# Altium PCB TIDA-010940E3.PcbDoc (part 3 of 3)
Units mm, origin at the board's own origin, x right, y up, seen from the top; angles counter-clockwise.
Board outline 71.12 x 63.5 mm, 2 copper layers (Top Layer, Bottom Layer), stack 1.382 mm thick; 136 components, 118 nets, 421 pads, 150 vias.
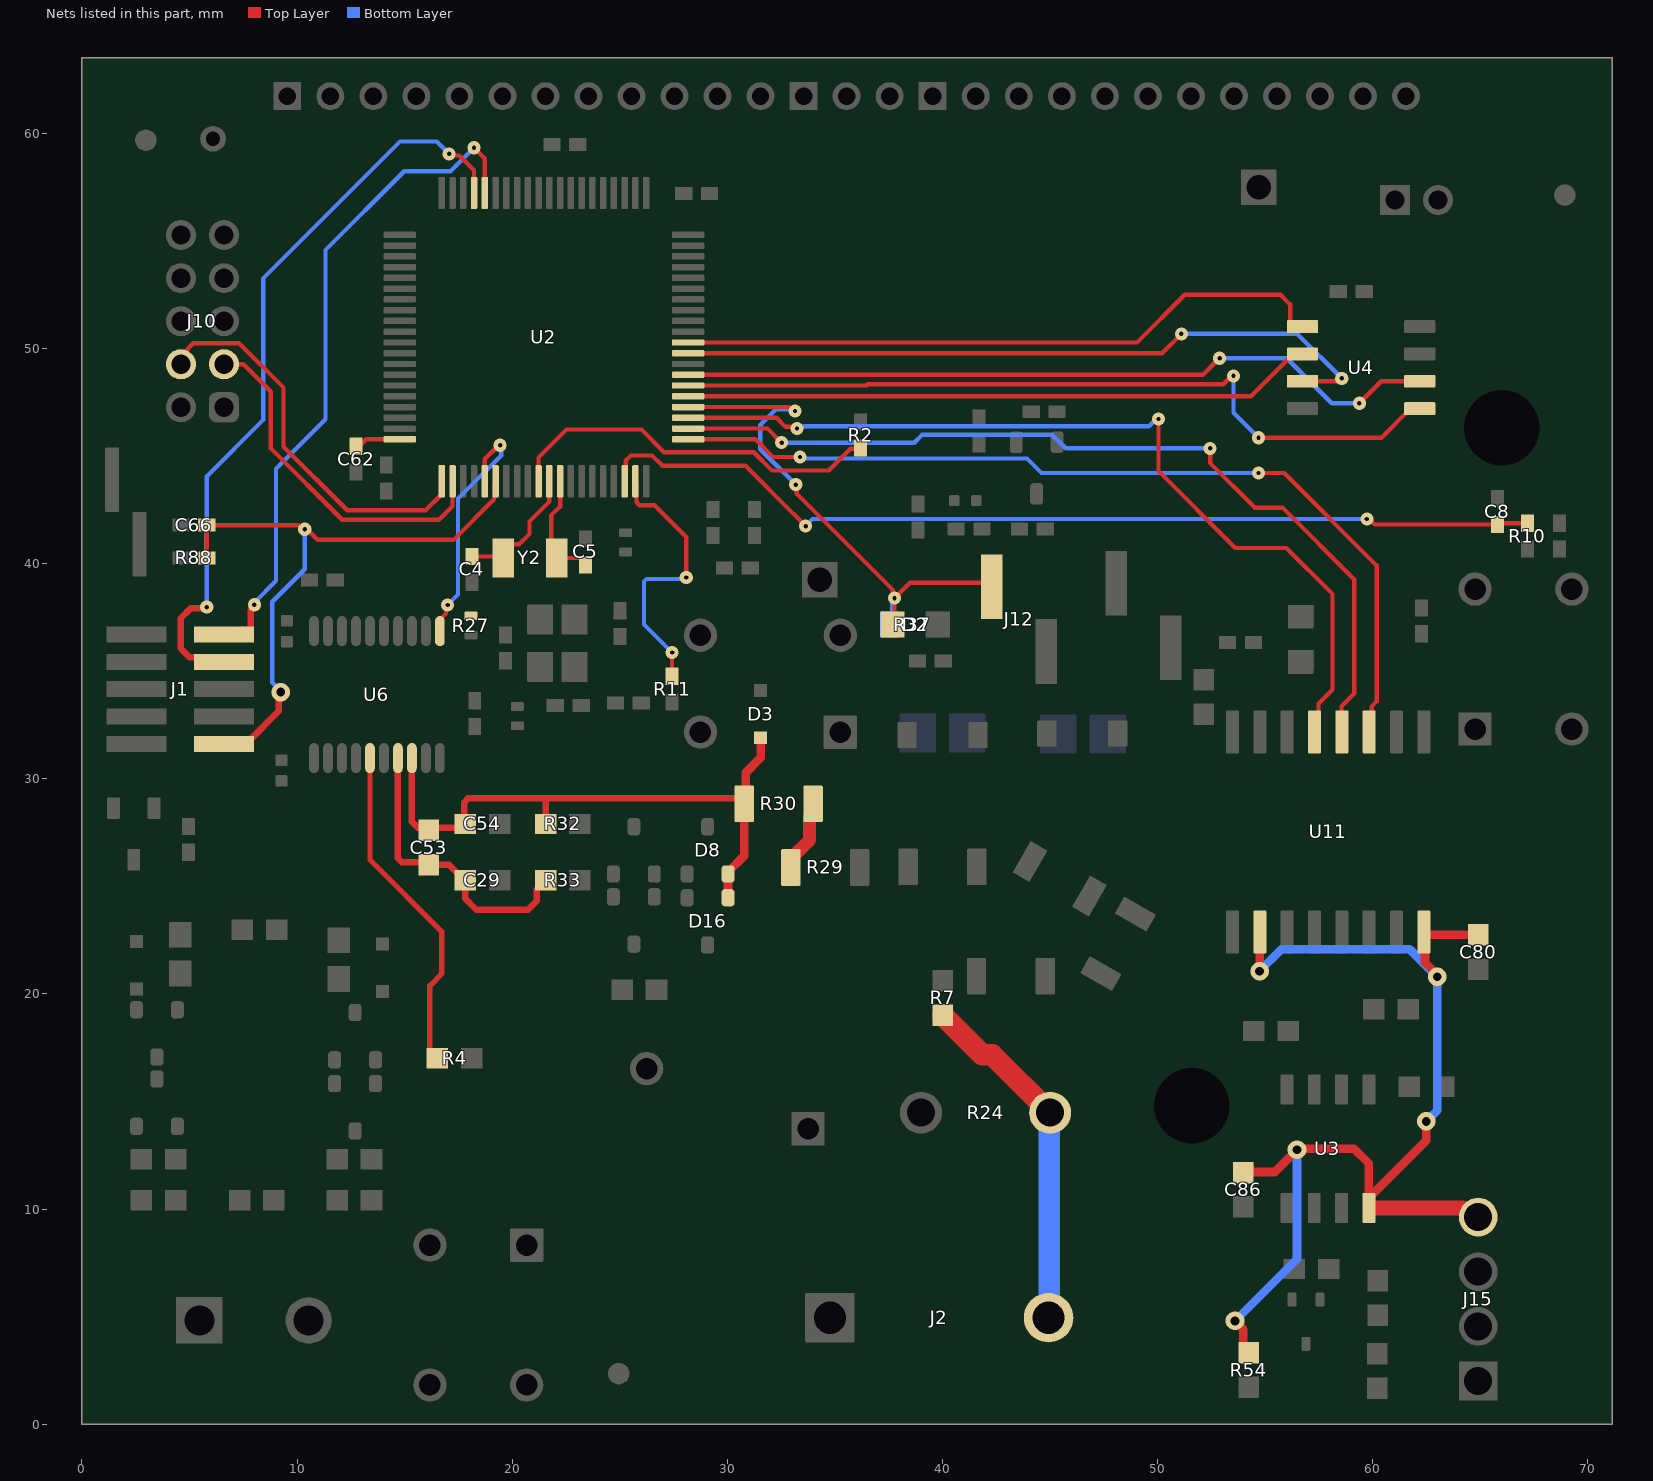
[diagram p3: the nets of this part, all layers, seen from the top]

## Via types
v1: diameter 0.61, hole 0.203, Top Layer to Bottom Layer, tented both sides, 113 vias
v2: diameter 0.61, hole 0.203, Top Layer to Bottom Layer, 22 vias
v3: diameter 0.864, hole 0.406, Top Layer to Bottom Layer, 8 vias
v4: diameter 0.864, hole 0.3, Top Layer to Bottom Layer, tented both sides, 4 vias
v5: diameter 0.864, hole 0.406, Top Layer to Bottom Layer, tented both sides, 3 vias

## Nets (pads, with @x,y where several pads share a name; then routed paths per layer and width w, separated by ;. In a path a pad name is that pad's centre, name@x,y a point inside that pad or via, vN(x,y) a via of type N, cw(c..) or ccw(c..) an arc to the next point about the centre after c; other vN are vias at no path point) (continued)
NetR29_1: R29.1 R30.1 | length 3.4
  Top Layer w0.6: R29.1@32.95,25.875 32.95,26.275 33.825,27.15 33.825,28.269 33.985,28.429 R30.1@33.985,28.829
nRST: C66.1 J1.10 R88.1 U2.6 | length 29.3
  Top Layer w0.2: R88.1@5.807,40.259 C66.1@5.807,41.775 ; C66.1@5.807,41.783 C66.1@5.807,41.775 ; U2.6@19.228,43.824 19.178,43.774 19.178,43.077 19.158,43.057 19.158,42.987 17.271,41.1 10.963,41.1 10.47,41.592 10.249,41.592 10.066,41.775 C66.1@5.807,41.775
  Top Layer w0.3: J1.10@6.607,31.623 6.786,31.802 7.811,31.802 9.152,33.143 9.152,33.927 v5(9.25,34.025)
  Bottom Layer w0.2: v5(9.25,34.025) 9.25,34.074 8.85,34.474 8.85,38.225 10.36,39.735 v1(10.36,41.592)
PA0: J10.4 U2.1 | length 18.5
  Top Layer w0.2: J10.4@4.604,49.262 4.604,49.587 4.91,49.893 4.91,49.971 5.182,50.242 7.308,50.242 9.375,48.175 9.375,45.431 12.331,42.475 15.979,42.475 16.728,43.224 U2.1@16.728,43.824
PA1: J10.3 U2.2 | length 16.6
  Top Layer w0.2: J10.3@6.604,49.262 7.509,49.262 8.786,47.985 8.786,45.351 12.102,42.036 16.598,42.036 17.228,42.665 U2.2@17.228,43.824
PA2_ROSC: R2.2 U2.10 | length 17.8
  Top Layer w0.2: U2.10@21.228,43.824 21.228,44.924 22.531,46.227 26.01,46.227 27.062,45.175 31.23,45.175 32.082,44.323 34.713,44.323 34.83,44.44 34.83,44.446 35.712,45.329 36.15,45.329 R2.2@36.195,45.374
PA3_LFXIN: C4.2 U2.11 Y2.2 | length 6.1
  Top Layer w0.2: C4.2@18.125,40.325 19.512,40.325 Y2.2@19.578,40.259 19.578,40.503 19.978,40.903 20.332,40.903 20.802,41.373 20.802,41.952 21.728,42.878 U2.11@21.728,43.824
PA4_LFXOUT: C5.2 U2.12 Y2.1 | length 5.2
  Top Layer w0.2: U2.12@22.228,43.824 22.228,42.646 21.811,42.229 21.811,40.526 Y2.1@22.078,40.259 23.168,40.259 23.368,40.059 C5.2@23.368,40.04
REACT: D2.1 J12.1 R37.1 U2.24 | length 24.8
  Top Layer w0.203: U2.24@28.178,47.274 32.849,47.274 33.032,47.091 v2(33.142,47.091) ; v2(33.179,43.668) 33.218,43.629 33.218,43.252 37.696,38.773 37.696,38.465 v1(37.77,38.391) ; D2.1@37.695,37.166 37.77,37.241 v1(37.77,38.391) ; J12.1@42.291,38.913 42.093,39.111 38.49,39.111 38.407,39.029 v1(37.77,38.391)
  Bottom Layer w0.203: v2(33.142,47.091) 33.065,47.168 32.262,47.168 31.535,46.442 31.535,45.312 v2(33.179,43.668) ; R37.1@37.666,37.291 v1@37.666,38.366
S\Y\N\C\/R\E\S\E\T\: U2.5 U6.11 | length 11.8
  Top Layer w0.2: U6.11@16.641,36.859 16.641,37.402 16.922,37.682 16.922,37.997 v1(17,38.075) ; U2.5@18.728,43.824 18.728,44.853 19.375,45.5 v1(19.439,45.5)
  Bottom Layer w0.2: v1(17,38.075) 17.484,38.559 17.484,43.02 19.489,45.024 19.489,45.45 v1(19.439,45.5)
Serial_RE_DE: U2.21 U11.3 | length 42.3
  Top Layer w0.2: U2.21@28.178,45.774 31.303,45.774 32.127,44.95 v1(33.375,44.95) ; v2(54.684,44.211) 55.883,44.211 60.178,39.916 60.178,33.591 59.943,33.356 59.943,32.288 U11.3@59.83,32.175
  Bottom Layer w0.2: v1(33.375,44.95) 33.442,44.883 43.929,44.883 44.601,44.211 v2(54.684,44.211)
Serial_RX: U2.23 U11.5 | length 41.9
  Top Layer w0.2: U2.23@28.178,46.774 32.288,46.774 32.71,46.353 33.161,46.353 v1(33.24,46.274) ; v2(50.038,46.72) 50.038,44.296 53.609,40.725 55.978,40.725 58.125,38.578 58.125,34.136 57.473,33.484 57.473,32.38 U11.5@57.277,32.184
  Bottom Layer w0.2: v1(33.24,46.274) 33.318,46.353 33.539,46.353 33.562,46.375 49.582,46.375 49.927,46.72 v2(50.038,46.72)
Serial_TX: U2.22 U11.4 | length 41.9
  Top Layer w0.2: U2.22@28.178,46.274 31.867,46.274 v1(32.523,45.618) ; v2(52.438,45.355) 52.438,44.674 54.512,42.6 55.8,42.6 59.134,39.266 59.134,33.957 58.547,33.37 U11.4@58.547,32.184
  Bottom Layer w0.2: v1(32.523,45.618) 38.687,45.618 39.048,45.979 45.1,45.979 45.725,45.355 v2(52.438,45.355)
SPI1_CS0: U2.30 U4.1 | length 30.6
  Top Layer w0.2: U2.30@28.178,50.274 49.041,50.274 51.262,52.495 55.706,52.495 56.157,52.044 56.157,51.212 56.357,51.012 U4.1@56.731,51.012
SPI1_PICO: U2.26 U4.5 | length 37
  Top Layer w0.203: U2.26@28.178,48.274 36.466,48.274 36.528,48.336 53.052,48.336 53.441,48.725 v1(53.525,48.725) v1@53.506,48.706 ; v1(54.684,45.845) 60.399,45.845 61.756,47.202 U4.5@62.181,47.202
  Bottom Layer w0.203: v1(53.525,48.725) 53.525,47.004 v1(54.684,45.845)
SPI1_POCI: U2.25 U4.2 | length 29.4
  Top Layer w0.2: U2.25@28.178,47.774 54.338,47.774 56.306,49.742 U4.2@56.731,49.742
SPI1_SCLK: U2.27 U4.6 | length 36.2
  Top Layer w0.2: U2.27@28.178,48.774 52.111,48.774 v1(52.881,49.544) ; v1(59.373,47.451) 60.394,48.472 U4.6@62.181,48.472
  Top Layer w0.203: 52.438,49.124 52.858,49.544 v1(52.881,49.544)
  Bottom Layer w0.2: v1(52.881,49.544) 55.999,49.544 58.092,47.451 v1(59.373,47.451)
SWCLK: J1.4 U2.57 | length 35.5
  Top Layer w0.2: v1(17.072,59.04) 17.151,58.961 17.544,58.961 18.228,58.278 U2.57@18.228,57.224
  Top Layer w0.3: v1(5.807,37.973) 5.749,37.915 5.052,37.915 4.591,37.454 4.591,36.054 5.009,35.636 6.404,35.636 J1.4@6.607,35.433
  Bottom Layer w0.2: v1(5.807,37.973) 5.807,44.051 8.425,46.669 8.425,53.25 14.792,59.617 16.494,59.617 v1(17.072,59.04)
SWDIO: J1.2 U2.56 | length 31.7
  Top Layer w0.2: v1@18.291,59.325 v1(18.225,59.325) 18.728,58.822 U2.56@18.728,57.224
  Top Layer w0.3: J1.2@6.607,36.703 7.155,36.703 7.375,36.923 7.852,36.923 7.852,37.832 8.02,38 v1(8.02,38.084)
  Bottom Layer w0.2: v1(8.02,38.084) 8.02,38.195 9.025,39.2 9.025,44.404 11.325,46.704 11.325,54.57 14.987,58.232 17.132,58.232 v1(18.225,59.325)
TAMPER_1: C8.1 R10.2 U2.18 | length 44.6
  Top Layer w0.2: U2.18@25.228,43.824 25.278,43.874 25.278,44.784 25.519,45.024 26.501,45.024 26.975,44.55 30.836,44.55 33.058,42.327 ; v2(59.722,42.072) 59.833,42.072 60.087,41.818 C8.1@65.786,41.818 65.843,41.875 R10.2@67.183,41.875
  Top Layer w0.203: 33.058,42.327 33.641,41.745 v1(33.641,41.742)
  Bottom Layer w0.2: v1(33.641,41.742) 33.641,41.75 33.962,42.072 v2(59.722,42.072)
TAMPER_2: R11.2 U2.19 | length 12.8
  Top Layer w0.2: U2.19@25.728,43.824 25.778,43.774 25.778,42.852 25.919,42.711 26.609,42.711 28.091,41.229 v1(28.091,39.35) ; R11.2@27.432,34.763 v1(27.432,35.865)
  Bottom Layer w0.2: v1(27.432,35.865) 26.129,37.167 26.129,39.162 26.246,39.279 28.02,39.279 v1(28.091,39.35)
V_PHASE_A: J2.2 R7.1 R24.1 | length 16.4
  Top Layer w1: R7.1@40.005,19.012 41.842,17.175 42.303,17.175 R24.1@45,14.478
  Bottom Layer w1: J2.2@44.93,4.95 44.965,4.985 44.965,14.443 R24.1@45,14.478
VCC_ISO_RS: C80.1 C86.1 J15.4 R54.2 U3.8 U11.10 U11.16 | length 52.5
  Top Layer w0.4: v3(53.594,4.801) 53.98,4.415 53.98,3.564 R54.2@54.229,3.315 ; C86.1@53.975,11.697 C86.1@53.975,11.722 ; C86.1@54.275,11.997 54.25,11.997 C86.1@53.975,11.722 ; v3(54.737,21.057) U11.10@54.737,22.708 ; v3(56.476,12.752) 55.446,11.722 C86.1@53.975,11.722 ; v3@56.476,12.802 59.13,12.802 59.817,12.115 U3.8@59.817,10.052 ; U3.8@59.917,10.152 59.917,10.616 62.484,13.183 v3(62.484,14.07) ; v3(62.996,20.792) 62.996,20.881 62.423,21.455 62.423,22.642 62.357,22.708 62.395,22.746 C80.1@64.897,22.746
  Top Layer w0.7: U3.8@60.066,10.052 64.174,10.052 64.599,9.627 J15.4@64.897,9.627
  Bottom Layer w0.4: v3(53.594,4.801) 56.476,7.683 v3(56.476,12.752) ; v3(54.737,21.057) 55.753,22.073 61.715,22.073 v3(62.996,20.792) 62.996,14.583 v3(62.484,14.07)
VCORE: C62.2 U2.80 | length 2
  Top Layer w0.2: C62.2@12.95,45.402 12.95,45.502 13.222,45.774 U2.80@14.778,45.774
VN: C29.2 C53.2 R33.2 U6.7 | length 13.8
  Top Layer w0.3: U6.7@14.691,30.959 14.691,26.3 14.867,26.124 C53.2@16.129,26.124 ; C53.2@16.129,25.997 17.068,25.997 17.792,25.273 C29.2@17.817,25.273 17.817,24.433 18.336,23.914 20.739,23.914 21.146,24.321 21.146,24.871 21.2,24.925 21.2,24.95 21.525,25.275 R33.2@21.55,25.275
VN_TMP63: R4.2 U6.5 | length 15.7
  Top Layer w0.25: U6.5@13.391,30.959 13.391,26.234 16.725,22.9 16.725,20.925 16.175,20.375 16.175,17.35 R4.2@16.525,17
VP: C53.1 C54.1 D3.2 D8.2 D16.1 R30.2 R32.2 U6.8 | length 29
  Top Layer w0.3: U6.8@15.341,30.959 15.341,28.004 15.621,27.724 16.129,27.724 17.704,27.724 17.742,27.686 17.767,27.686 17.767,28.907 17.943,29.083 21.552,29.083 21.667,29.083 ; R32.2@21.552,27.686 21.552,28.968 21.667,29.083 ; R30.2@30.451,29.083 21.667,29.083
  Top Layer w0.4: D16.1@30.033,24.468 D8.2@30.033,25.57 30.033,25.67 30.785,26.422 R30.2@30.785,28.829 30.854,28.898 30.854,30.279 31.547,30.972 D3.2@31.547,31.902
WP_FLASH: U2.29 U4.3 | length 33.5
  Top Layer w0.203: U2.29@28.178,49.774 50.205,49.774 v1(51.104,50.673) ; U4.3@56.731,48.472 58.421,48.472 v1(58.556,48.607)
  Bottom Layer w0.203: v1(51.104,50.673) 56.49,50.673 v1(58.556,48.607)
XO_HFX: R27.1 | length 0.1
  Top Layer w0.2: R27.1@18.082,37.569 R27.1@18.182,37.569
pads on no net: D6.1 D7.3 D8.3 D10.2 D12.3 D14.3 D15.3 D16.3 FID1.1 FID2.1 FID3.1 H1. H2. J1.6 J1.7 J1.8 LBL1.0 U2.20 U6.9 U6.10 U11.6 U11.11 Y1.2

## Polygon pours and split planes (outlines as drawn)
DGND on Top Layer "TOP_LAYER_DGND_P005" (solid, remove dead copper, pour order 5): 0.889,62.57 0.889,39.751 0.889,31.369 36.755,31.369 70.485,31.369 70.485,62.57
GND_ISO_RS on Top Layer "TOP_LAYER_GND_ISO_RS_P000" (solid, remove dead copper, pour order 0): 52.916,23.724 52.916,0.356 70.231,0.356 70.231,23.724
GND_ISO_RS on Bottom Layer "BOTTOM_LAYER_GND_ISO_RS_P003" (solid, remove dead copper, pour order 3): 53.284,23.597 67.818,23.597 70.231,23.597 70.231,0.483 53.284,0.483
DGND on Bottom Layer "BOTTOM_LAYER_DGND_P004" (solid, remove dead copper, pour order 4): 1.305,62.323 1.305,39.504 1.305,31.122 37.171,31.122 70.901,31.122 70.901,62.323

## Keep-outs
Keep-Out Layer:
  lines w0.254: 0,63.5 0,0 71.12,0
  text ".Layer_Name" at 11.481,-29.045 h1.52

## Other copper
Top Layer:
  text ".Layer_Name" at 11.481,-29.045 h1.52
Bottom Layer:
  text ".Layer_Name" at 11.481,-29.045 h1.52

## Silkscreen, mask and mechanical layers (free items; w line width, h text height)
Top Overlay:
  circle w0.2: c43.942,49.389 r10.2
  text "1-phase SHUNT E-meter" at 23.775,65.776 h2
  text "2mm, 27 pins row" at 54.857,59.588 h0.76
  text "GND" at 65.423,55.827 h0.76 r90
  text "'.PRJ_Number'.PCB_Rev" at 38.188,55.08 h1.91
  text "3V3" at 59.727,54.702 h0.76
  text "BAT-" at 56.809,53.355 h0.76 r90
  text "2mm 5x2" at 9.323,49.277 h0.76 r90
  text "GND" at 1.392,46.095 h0.76 r90
  text "VBAT +" at 32.837,40.573 h0.76 r90
  text "3V3" at 2.635,38.252 h0.76
  text "MENU SW" at 32.627,34.252 h0.76
  text "GND_ISO" at 63.148,19.083 h0.76
  text "DGND" at 8.776,13.106 h0.76 r90
  text "ISO_V" at 64.552,11.854 h0.76
  text "ISO_G" at 67.721,5.902 h0.76 r90
  text "B" at 67.618,3.929 h0.76 r90
  text "CURRENT" at 1.575,1.925 h1 r90
  text "A" at 67.618,1.389 h0.76 r90
  text "DGND" at 31.423,1.277 h0.76 r90
  text "VOLTAGE" at 50.3,0.847 h1.3 r90
  text ".Layer_Name" at 11.481,-29.045 h1.52
Bottom Overlay:
  text ".Layer_Name" at 11.481,-29.045 h1.52
Top Paste:
  text ".Layer_Name" at 11.481,-29.045 h1.52
Bottom Paste:
  text ".Layer_Name" at 11.481,-29.045 h1.52
Top Solder:
  text ".Layer_Name" at 11.481,-29.045 h1.52
  text ".Layer_Name" at 11.481,-29.045 h1.52
Bottom Solder:
  text ".Layer_Name" at 11.481,-29.045 h1.52
Drill Guide:
  text ".Layer_Name" at 11.481,-29.045 h1.52
M1 Board Outline:
  the board outline again, w0.254
  text ".Layer_Name" at 11.481,-29.045 h1.52
M2 Board Dimensions:
  rectangle: -3.175,-14.224 0,-11.049
  rectangle: 0,-17.399 9.525,-14.224
  lines w0.178: -3.175,-14.224 22.225,-14.224 ; 0,-17.399 0,-11.049 ; 3.175,-17.399 3.175,-11.049 ; 9.525,-17.399 9.525,-11.049 ; 15.875,-17.399 15.875,-11.049 ; -3.175,-17.399 22.225,-17.399 22.225,-11.049 -3.175,-11.049 -3.175,-17.399
  lines w0.254: -3.172,1.525 -2.667,0 ; -3.051,61.85 -2.54,63.373 ; -2.921,0.001 -2.413,-0.001 ; -2.794,63.374 -2.286,63.372 ; -2.622,22.266 -2.667,0 ; -2.585,41.107 -2.54,63.373 ; -2.156,1.523 -2.667,0 ; -2.035,61.848 -2.54,63.373 ; 34.127,40.931 34.453,40.542 ; 35.131,42.105 34.29,40.736 ; 35.784,41.327 34.29,40.736 ; 36.185,42.327 34.29,40.736 ; 50.81,54.606 52.705,56.197 ; 51.211,55.606 52.705,56.197 ; 51.864,54.828 52.705,56.197 ; 52.542,56.392 52.868,56.002
  text "24.04479 (mm)" at 36.968,41.791 h1.52 r40.02
  text "63.37313 (mm)" at -1.708,22.518 h1.52 r89.89
  text ".Layer_Name" at 11.481,-29.045 h1.52
M3 3D STEP Top:
  drawing of 1303 lines, arcs and shapes, not listed
  text ".Layer_Name" at 11.481,-29.045 h1.52
M4 3D STEP Bottom:
  text ".Layer_Name" at 11.481,-29.045 h1.52
M5 Assembly Top:
  lines w0.254: -10.592,-30.865 157.048,-30.865 ; -10.592,-25.701 157.099,-25.701 ; -10.592,-20.536 -10.592,-36.03 91.135,-36.03 157.099,-36.03 157.099,-20.536 -10.579,-20.536 -10.579,-36.03 29.439,-36.03 ; 52.019,-36.03 52.019,-20.536 ; 84.201,-25.701 84.201,-20.536 ; 105.537,-25.701 105.537,-20.536 ; 121.336,-36.195 121.336,-31.043
  text "COMPONENTS MARKED 'DNP' SHOULD NOT BE POPULATED." at 26.124,-15.329 h1.52
  text "ASSEMBLY VARIANT:" at 26.111,-18.263 h1.52
  text ".VariantName" at 52.426,-18.263 h1.52
  text "PCB VIEWED FROM TOP SIDE" at -8.979,-23.893 h1.52
  text "BOARD #:" at 53.924,-23.893 h1.52
  text ".PRJ_Number" at 67.78,-23.893 h1.52
  text "REV:" at 89.23,-23.893 h1.52
  text ".PCB_Rev" at 96.634,-23.893 h1.52
  text "SVN REV:" at 110.515,-23.893 h1.52
  text ".VersionControl_RevNumber" at 123.368,-23.893 h1.52
  text "TID #:" at 53.924,-29.058 h1.52
  text ".TID" at 67.78,-29.058 h1.52
  text "PLOT NAME =" at -8.979,-34.273 h1.52
  text ".plot_File_Name" at 11.481,-34.273 h1.52
  text "GENERATED    :" at 53.975,-34.273 h1.52
  text ".Print_Date" at 76.06,-34.273 h1.52
  text ".Print_Time" at 94.577,-34.273 h1.52
  text "TEXAS INSTRUMENTS" at 126.695,-34.273 h1.52
M6 Assembly Bottom:
  lines w0.254: -10.604,-25.713 157.086,-25.713 ; -10.554,-30.878 157.086,-30.878 ; 25.159,-36.208 25.159,-31.056 ; 40.957,-25.713 40.957,-20.549 ; 62.293,-25.713 62.293,-20.549 ; 94.475,-36.043 94.475,-20.549 ; 117.056,-36.043 157.074,-36.043 157.074,-20.549 -10.604,-20.549 -10.604,-36.043 55.359,-36.043 157.086,-36.043 157.086,-20.549
  text "COMPONENTS MARKED 'DNP' SHOULD NOT BE POPULATED." at 151.816,-15.316 h1.52
  text ".VariantName" at 125.298,-18.263 h1.52
  text "ASSEMBLY VARIANT:" at 151.689,-18.263 h1.52
  text ".VersionControl_RevNumber" at 23.127,-23.906 h1.52
  text "SVN REV:" at 35.979,-23.906 h1.52
  text ".PCB_Rev" at 49.86,-23.906 h1.52
  text "REV:" at 57.264,-23.906 h1.52
  text ".PRJ_Number" at 78.715,-23.906 h1.52
  text "BOARD #:" at 92.57,-23.906 h1.52
  text "PCB VIEWED FROM BOTTOM SIDE" at 155.473,-23.906 h1.52
  text ".TID" at 78.715,-29.07 h1.52
  text "TID #:" at 92.57,-29.07 h1.52
  text "TEXAS INSTRUMENTS" at 19.799,-34.286 h1.52
  text ".Print_Time" at 51.918,-34.286 h1.52
  text ".Print_Date" at 70.434,-34.286 h1.52
  text "GENERATED    :" at 92.519,-34.286 h1.52
  text ".plot_File_Name" at 135.014,-34.286 h1.52
  text "PLOT NAME =" at 155.473,-34.286 h1.52
M9 Title Sheet:
  drawing of 57 lines, arcs and shapes, not listed
  text "1" at 15.617,196.888 h1.78
  text "2" at 79.007,196.888 h1.78
  text "3" at 142.236,196.888 h1.78
  text "4" at 205.905,196.888 h1.78
  text "5" at 269.38,196.888 h1.78
  text "6" at 333.007,196.888 h1.78
  text "A" at -13.754,167.856 h1.78
  text "A" at 362.166,167.856 h1.78
  text "B" at -13.754,107.404 h1.78
  text "B" at 362.166,107.404 h1.78
  text "C" at -13.754,47.079 h1.78
  text "C" at 362.166,47.079 h1.78
  text "PROJECT TITLE:" at 284.95,-0.191 h1.14
  text ".PRJ_Title" at 286.22,-3.577 h1.78
  text "DESIGNED FOR:" at 284.95,-7.836 h1.14
  text ".PRJ_Customer" at 286.22,-11.392 h1.78
  text "D" at -13.754,-13.119 h1.78
  text "D" at 362.166,-13.119 h1.78
  text "FILE NAME:" at 284.95,-15.456 h1.14
  text ".PCB_File_Name_No_Path" at 286.22,-18.504 h1.78
  text "Texas Instruments (TI) and/or its licensors do not warrant the accuracy or completeness of this specification" at 158.725,-22.615 h1.14
  text "ENGINEER:" at 284.95,-22.822 h1.14
  text "LAYOUT BY:" at 323.177,-22.822 h1.14
  text "or any information contained therein. TI and/or its licensors do not warrant that this design will meet" at 157.582,-25.476 h1.14
  text ".PRJ_Engineer" at 286.22,-26.759 h1.78
  text ".PCB_Layout" at 324.46,-26.759 h1.78
  text "the specifications, will be suitable for your application or fit for any particular purpose, or will operate in" at 157.582,-28.338 h1.14
  text ".Layer_Name" at 11.481,-29.045 h1.52
  text "ALTIUM DESIGNER VERSION:" at 323.177,-30.696 h1.14
  text "an implementation. TI and/or its licensors do not warrant that the design is production worthy. You should" at 157.582,-31.2 h1.14
  text "completely validate and test your design implementation to confirm the system functionality for your application." at 158.725,-34.061 h1.14
  text ".print_Scale" at 286.22,-34.082 h1.78
  text ".Application_BuildNumber" at 324.46,-34.082 h1.78
  text "1" at 15.617,-39.332 h1.78
  text "2" at 79.007,-39.332 h1.78
  text "3" at 142.236,-39.332 h1.78
  text "4" at 205.905,-39.332 h1.78
  text "5" at 269.38,-39.332 h1.78
  text "6" at 333.007,-39.332 h1.78
M10 Fab Notes:
  drawing of 189 lines, arcs and shapes, not listed
  text "DESIGN INFORMATION" at 311.328,154.208 h1.52
  text "MIN. TRACK WIDTH:" at 294.956,150.852 h1.52
  text "8" at 322.801,150.852 h1.52
  text "MIL" at 326.732,150.852 h1.52
  text "7.874" at 318.575,147.761 h1.52
  text "MIN. CLEARANCE:" at 294.956,147.699 h1.52
  text "MIL" at 326.732,147.699 h1.52
  text "MIN. VIA PAD SIZE:" at 294.956,144.546 h1.52
  text "24" at 322.039,144.546 h1.52
  text "MIL" at 326.732,144.546 h1.52
  text "0.05mm (2MIL)" at 312.609,141.247 h1.52
  text "MINIMUM ANNULAR RING" at 286.594,141.038 h1.52
  text "EXTERNAL" at 330.593,141.038 h1.52
  text "PER" at 291.674,138.241 h1.52
  text "IPC-D-275 CLASS 2 LEVEL C" at 297.262,138.241 h1.52
  text "MIL, HOLES" at 335.063,135.689 h1.52
  text "+/-" at 325.095,135.47 h1.52
  text "+/-" at 346.786,135.47 h1.52
  text "REGISTRATION TOLERANCES:" at 286.594,135.443 h1.52
  text "METAL" at 317.068,135.443 h1.52
  text "5" at 331.704,135.444 h1.52
  text "3" at 352.862,135.444 h1.52
  text "MIL" at 355.815,135.443 h1.52
  text "HOLE SIZE TOLERANCE (UNLESS OTHERWISE SPECIFIED):" at 286.594,132.946 h1.52
  text "+/-" at 346.786,132.873 h1.52
  text "3" at 352.862,132.846 h1.52
  text "MIL" at 355.815,132.846 h1.52
  text "MATERIAL:" at 284.695,129.35 h1.52
  text "FR-4 High Tg" at 309.751,126.085 h1.52
  text "X" at 306.082,125.883 h1.52
  text "FR-408" at 295.388,125.768 h1.52
  text "OTHER" at 333.183,125.768 h1.52
  text "62 MIL (1.6mm) +/-10%" at 303.519,122.135 h1.52
  text "X" at 300.468,122.073 h1.52
  text "THICKNESS:" at 286.594,121.926 h1.52
  text "OTHER" at 336.155,121.926 h1.52
  text "TOLERANCE:" at 286.594,118.413 h1.52
  text "X" at 308.139,118.413 h1.52
  text "ANSI IPC-6012 TYPE 3 CLASS 2" at 312.661,118.413 h1.52
  text "OTHER +/-" at 312.66,114.75 h1.52
  text "BOW & TWIST:" at 286.594,111.063 h1.52
  text "X" at 308.139,111.063 h1.52
  text "ANSI IPC-6012 TYPE 3 CLASS 2" at 312.661,111.063 h1.52
  text "OTHER +/-" at 312.66,107.337 h1.52
  text "DRILLING:" at 284.695,104.019 h1.52
  text "NC_DRILL FILES" at 329.424,101.347 h1.52
  text "REFERENCE:" at 286.594,101.247 h1.52
  text "X" at 303.288,101.245 h1.52
  text "AS SHOWN" at 307.809,101.247 h1.52
  text "X" at 326.173,101.247 h1.52
  text "OTHER" at 336.993,97.634 h1.52
  text "PTH COPPER THICKNESS:" at 286.586,97.544 h1.52
  text "X" at 315.522,97.544 h1.52
  text "20-30 um" at 318.773,97.544 h1.52
  text "BOARD FINISH:" at 284.695,93.795 h1.52
  text "SILKSCREEN:" at 288.637,90.998 h1.52
  text "X" at 312.965,90.998 h1.52
  text "TOP" at 315.937,90.998 h1.52
  text "X" at 325.919,90.998 h1.52
  text "BOTTOM" at 328.916,90.998 h1.52
  text "SILKSCREEN COLOR:" at 288.637,87.056 h1.52
  text "X" at 312.94,87.056 h1.52
  text "WHITE" at 315.937,87.056 h1.52
  text "OTHER" at 328.916,87.056 h1.52
  text "X" at 316.267,83.413 h1.52
  text "GREEN" at 319.264,83.413 h1.52
  text "OTHER" at 334.961,83.413 h1.52
  text "SOLDER RESIST COLOR:" at 288.637,83.238 h1.52
  text "X" at 316.267,79.495 h1.52
  text "MATTE" at 319.264,79.495 h1.52
  text "SEMI-GLOSS" at 334.95,79.478 h1.52
  text "IMMERSION GOLD (ENIG)" at 311.644,75.106 h1.52
  text "ENEPIG" at 345.618,74.923 h1.52
  text "SURFACE FINISH:" at 284.695,74.897 h1.52
  text "X" at 307.123,74.897 h1.52
  text "IMM. TIN/SILVER OR EQUIV" at 293.065,71.41 h1.52
  text "OTHER" at 329.424,71.31 h1.52
  text "ARRAY/PANEL:" at 284.695,67.363 h1.52
  text "CUT AND TRIM PER M1 BOARD OUTLINE" at 311.644,67.154 h1.52
  text "N.C. ROUTE" at 311.644,63.701 h1.52
  text "X" at 329.12,63.701 h1.52
  text "V. SCORE" at 333.641,63.701 h1.52
  text "CERTIFICATION:" at 284.695,60.421 h1.52
  text "MATERIALS AND WORKMANSHIP FOR ALL PCBS" at 303.11,60.421 h1.52
  text "TO MEET OR EXCEED THE REQUIREMENTS OF:" at 303.11,58.032 h1.52
  text "X" at 293.903,54.764 h1.52
  text "ANSI IPC-A-600F CLASS ->" at 297.154,54.764 h1.52
  text "X" at 339.013,54.764 h1.52
  text "2" at 341.807,54.764 h1.52
  text "1" at 333.806,54.726 h1.52
  text "3" at 350.798,54.726 h1.52
  text "X" at 314.527,51.013 h1.52
  text "RoHS" at 317.778,51.013 h1.52
  text "OTHER" at 334.146,51.013 h1.52
  text "PER ORDER" at 344.232,51.013 h1.52
  text "ALL BOARDS MUST MEET OR EXCEED UL94-V0 REQUIREMENTS." at 285.394,47.106 h1.52
  text "PCB MUST BEAR THE UL94V-0 UL REGISTERED MATERIAL ID NUMBER" at 285.394,44.158 h1.52
  text "ADDITIONAL REQUIREMENTS:" at 284.695,39.855 h1.52
  text "MICROSECTION:" at 286.594,37.134 h1.52
  text "YES" at 309.6,37.134 h1.52
  text "REQUIRED" at 331.482,33.468 h1.52
  text "BARE BOARD ELEC. TEST:" at 286.594,33.395 h1.52
  text "NONE" at 319.76,33.395 h1.52
  text "X" at 328.485,33.395 h1.52
  text "PER ORDER" at 346.518,33.395 h1.52
  text "XX MIL VIAS REQUIRE NON-CONDUCTIVE FILL AND PLANARIZE" at 290.865,28.189 h1.5
  text "XX MIL VIAS REQUIRE CONDUCTIVE FILL AND PLANARIZE" at 291.068,25.548 h1.52
  text "OUTER XX MIL TRACES REQUIRE 50 OHM SINGLE-ENDED IMPEDANCE" at 291.043,21.398 h1.47
  text "LAYER 2 & 3 (INNER LAYERS) XX MIL WIDE, XX MIL SPACE / TRACES REQUIRE 100 OHM DIFFERENTIAL IMPEDANCE" at 290.84,15.411 h1.52
  text ".Layer_Name" at 11.481,-29.045 h1.52
M11 Gerber Information:
  lines w0.254: -10.592,-30.865 157.048,-30.865 ; -10.592,-25.701 157.099,-25.701 ; -10.592,-20.536 -10.592,-36.03 91.135,-36.03 157.099,-36.03 157.099,-20.536 -10.579,-20.536 -10.579,-36.03 29.439,-36.03 ; 52.019,-36.03 52.019,-20.536 ; 84.201,-25.701 84.201,-20.536 ; 105.537,-25.701 105.537,-20.536 ; 121.336,-36.195 121.336,-31.043
  text "ALL ARTWORK VIEWED FROM TOP SIDE" at -8.979,-23.893 h1.52
  text "BOARD #:" at 53.924,-23.893 h1.52
  text ".PRJ_Number" at 67.78,-23.893 h1.52
  text "REV:" at 89.23,-23.893 h1.52
  text ".PCB_Rev" at 96.634,-23.893 h1.52
  text "SVN REV:" at 110.515,-23.893 h1.52
  text ".VersionControl_RevNumber" at 123.368,-23.893 h1.52
  text "LAYER NAME =" at -8.979,-29.045 h1.52
  text "TID #:" at 53.924,-29.058 h1.52
  text ".TID" at 67.78,-29.058 h1.52
  text "PLOT NAME =" at -8.979,-34.273 h1.52
  text ".plot_File_Name" at 11.481,-34.273 h1.52
  text "GENERATED    :" at 53.975,-34.273 h1.52
  text ".Print_Date" at 76.06,-34.273 h1.52
  text ".Print_Time" at 94.577,-34.273 h1.52
  text "TEXAS INSTRUMENTS" at 126.695,-34.273 h1.52
M12 Stackup:
  drawing of 217 lines, arcs and shapes, not listed
  text "Layer" at 146.446,137.795 h1.52
  text "Name" at 156.857,137.795 h1.52
  text "Material" at 180.473,137.795 h1.52
  text "Thickness" at 212.468,137.795 h1.52
  text "Constant" at 228.974,137.795 h1.52
  text "Board Layer Stack" at 243.448,137.795 h1.52
  text "Top Overlay" at 156.857,134.747 h1.52
  text "Top Solder" at 156.857,131.699 h1.52
  text "Solder Resist" at 180.473,131.699 h1.52
  text "0.40mil" at 212.468,131.699 h1.52
  text "3.5" at 228.974,131.699 h1.52
  text "1" at 146.446,128.651 h1.52
  text "Top Layer" at 156.857,128.651 h1.52
  text "1.40mil" at 212.468,128.651 h1.52
  text "Dielectric 2" at 156.857,125.603 h1.52
  text "FR-4 High Tg" at 180.473,125.603 h1.52
  text "39.00mil" at 212.468,125.603 h1.52
  text "4.8" at 228.974,125.603 h1.52
  text "Dielectric2" at 156.857,122.555 h1.52
  text "Composite dielectric" at 180.473,122.555 h1.52
  text "12.60mil" at 212.468,122.555 h1.52
  text "4.8" at 228.974,122.555 h1.52
  text "2" at 146.446,119.507 h1.52
  text "Bottom Layer" at 156.857,119.507 h1.52
  text "1.40mil" at 212.468,119.507 h1.52
  text "Bottom Solder" at 156.857,116.459 h1.52
  text "Solder Resist" at 180.473,116.459 h1.52
  text "0.40mil" at 212.468,116.459 h1.52
  text "3.5" at 228.974,116.459 h1.52
  text "Bottom Overlay" at 156.857,113.411 h1.52
  text ".Layer_Name" at 11.481,-29.045 h1.52
M13 Component Bodies Top:
  text ".Layer_Name" at 11.481,-29.045 h1.52
M14 Component Bodies Bottom:
  text ".Layer_Name" at 11.481,-29.045 h1.52
M15 Courtyards Top:
  text ".Layer_Name" at 11.481,-29.045 h1.52
M16 Courtyards Bottom:
  text ".Layer_Name" at 11.481,-29.045 h1.52
Drill Drawing:
  circle w0.254: c148.637,85.345 r0.421
  circle w0.254: c148.637,85.345 r0.702
  circle w0.254: c148.637,82.188 r0.702
  lines w0.254: 147.935,47.102 148.286,47.102 148.637,46.751 148.988,47.102 149.338,47.102 148.988,47.453 149.338,47.804 148.988,47.804 148.637,48.154 148.286,47.804 147.935,47.804 148.286,47.453 147.935,47.102 ; 147.935,50.26 148.286,50.26 148.286,49.909 148.988,49.909 148.988,50.26 149.338,50.26 149.338,50.961 148.988,50.961 148.988,51.312 148.286,51.312 148.286,50.961 147.935,50.961 147.935,50.26 ; 147.935,53.066 149.338,53.066 149.338,54.47 147.935,54.47 147.935,53.066 ; 147.935,57.628 149.338,57.628 148.637,56.224 147.935,57.628 ; 147.935,59.382 148.637,59.733 149.338,59.382 148.988,60.084 149.338,60.785 148.637,60.434 147.935,60.785 148.286,60.084 147.935,59.382 ; 147.935,62.54 147.935,62.89 148.286,63.241 147.935,63.592 147.935,63.943 148.286,63.943 148.637,63.592 148.988,63.943 149.338,63.943 149.338,63.592 148.988,63.241 149.338,62.89 149.338,62.54 148.988,62.54 148.637,62.89 148.286,62.54 147.935,62.54 ; 147.935,66.399 148.637,65.697 149.338,66.399 148.637,67.101 147.935,66.399 ; 147.935,69.206 148.286,69.206 148.637,68.855 148.988,69.206 149.338,69.206 148.988,69.557 149.338,69.908 148.988,69.908 148.637,70.259 148.286,69.908 147.935,69.908 148.286,69.557 147.935,69.206 ; 147.935,72.013 148.637,72.364 149.338,72.013 148.988,72.715 149.338,73.416 148.637,73.065 147.935,73.416 148.286,72.715 147.935,72.013 ; 147.935,75.171 149.338,75.171 149.338,76.574 147.935,76.574 147.935,75.171 ; 147.935,79.732 149.338,79.732 148.637,78.328 147.935,79.732 ; 148.216,53.347 149.058,53.347 149.058,54.189 148.216,54.189 148.216,53.347 ; 148.216,57.347 149.058,57.347 148.637,56.505 148.216,57.347 ; 148.216,69.346 148.426,69.346 148.637,69.136 148.847,69.346 149.058,69.346 148.847,69.557 149.058,69.767 148.847,69.767 148.637,69.978 148.426,69.767 148.216,69.767 148.426,69.557 148.216,69.346 ; 148.216,72.293 148.637,72.504 149.058,72.293 148.847,72.715 149.058,73.136 148.637,72.925 148.216,73.136 148.426,72.715 148.216,72.293
  lines w0.305: 146.663,45.804 228.742,45.804 ; 146.663,86.854 228.742,86.854 ; 155.244,42.646 155.244,90.012 ; 163.677,42.646 163.677,90.012 ; 179.846,42.646 179.846,90.012 ; 186.428,42.646 186.428,90.012 ; 195.957,42.646 195.957,90.012 ; 214.355,42.646 214.355,90.012 ; 146.663,42.646 228.742,42.646 228.742,90.012 146.663,90.012 146.663,42.646
  text "Symbol" at 148.557,87.801 h1.83
  text "Quantity" at 156.192,87.801 h1.83
  text "Finished Hole Size" at 164.624,87.801 h1.83
  text "Plated" at 180.793,87.801 h1.83
  text "Hole Type" at 187.375,87.801 h1.83
  text "Drill Layer Pair" at 196.904,87.801 h1.83
  text "Hole Tolerance" at 215.302,87.801 h1.83
  text "2" at 156.192,84.644 h1.52
  text "137.79mil (3.500mm)" at 164.624,84.644 h1.52
  text "NPTH" at 180.793,84.644 h1.52
  text "Round" at 187.375,84.644 h1.52
  text "Top Layer - Bottom Layer" at 196.904,84.644 h1.52
  text "135" at 156.192,81.486 h1.52
  text "8.00mil (0.203mm)" at 164.624,81.486 h1.52
  text "PTH" at 180.793,81.486 h1.52
  text "Round" at 187.375,81.486 h1.52
  text "Top Layer - Bottom Layer" at 196.904,81.486 h1.52
  text "4" at 156.192,78.328 h1.52
  text "11.81mil (0.300mm)" at 164.624,78.328 h1.52
  text "PTH" at 180.793,78.328 h1.52
  text "Round" at 187.375,78.328 h1.52
  text "Top Layer - Bottom Layer" at 196.904,78.328 h1.52
  text "11" at 156.192,75.171 h1.52
  text "16.00mil (0.406mm)" at 164.624,75.171 h1.52
  text "PTH" at 180.793,75.171 h1.52
  text "Round" at 187.375,75.171 h1.52
  text "Top Layer - Bottom Layer" at 196.904,75.171 h1.52
  text "1" at 156.192,72.013 h1.52
  text "25.98mil (0.660mm)" at 164.624,72.013 h1.52
  text "PTH" at 180.793,72.013 h1.52
  text "Round" at 187.375,72.013 h1.52
  text "Top Layer - Bottom Layer" at 196.904,72.013 h1.52
  text "24" at 156.192,68.855 h1.52
  text "31.50mil (0.800mm)" at 164.624,68.855 h1.52
  text "PTH" at 180.793,68.855 h1.52
  text "Round" at 187.375,68.855 h1.52
  text "Top Layer - Bottom Layer" at 196.904,68.855 h1.52
  text "3" at 156.192,65.697 h1.52
  text "31.89mil (0.810mm)" at 164.624,65.697 h1.52
  text "PTH" at 180.793,65.697 h1.52
  text "Round" at 187.375,65.697 h1.52
  text "Top Layer - Bottom Layer" at 196.904,65.697 h1.52
  text "+/-1.97mil" at 215.302,65.697 h1.52
  text "12" at 156.192,62.54 h1.52
  text "35.04mil (0.890mm)" at 164.624,62.54 h1.52
  text "PTH" at 180.793,62.54 h1.52
  text "Round" at 187.375,62.54 h1.52
  text "Top Layer - Bottom Layer" at 196.904,62.54 h1.52
  text "14" at 156.192,59.382 h1.52
  text "39.37mil (1.000mm)" at 164.624,59.382 h1.52
  text "PTH" at 180.793,59.382 h1.52
  text "Round" at 187.375,59.382 h1.52
  text "Top Layer - Bottom Layer" at 196.904,59.382 h1.52
  text "2" at 156.192,56.224 h1.52
  text "45.28mil (1.150mm)" at 164.624,56.224 h1.52
  text "PTH" at 180.793,56.224 h1.52
  text "Round" at 187.375,56.224 h1.52
  text "Top Layer - Bottom Layer" at 196.904,56.224 h1.52
  text "6" at 156.192,53.066 h1.52
  text "51.18mil (1.300mm)" at 164.624,53.066 h1.52
  text "PTH" at 180.793,53.066 h1.52
  text "Round" at 187.375,53.066 h1.52
  text "Top Layer - Bottom Layer" at 196.904,53.066 h1.52
  text "2" at 156.192,49.909 h1.52
  text "55.12mil (1.400mm)" at 164.624,49.909 h1.52
  text "PTH" at 180.793,49.909 h1.52
  text "Round" at 187.375,49.909 h1.52
  text "Top Layer - Bottom Layer" at 196.904,49.909 h1.52
  text "2" at 156.192,46.751 h1.52
  text "59.06mil (1.500mm)" at 164.624,46.751 h1.52
  text "PTH" at 180.793,46.751 h1.52
  text "Round" at 187.375,46.751 h1.52
  text "Top Layer - Bottom Layer" at 196.904,46.751 h1.52
  text "218 Total" at 156.192,43.593 h1.52
  text ".Layer_Name" at 11.481,-29.045 h1.52
M17 Embedded Cavity:
  text ".Layer_Name" at 11.481,-29.045 h1.52
M18 Embedded Assembly:
  text ".Layer_Name" at 11.481,-29.045 h1.52
M19 Embedded Keepout:
  text ".Layer_Name" at 11.481,-29.045 h1.52

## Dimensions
0,-2.159 to 71.12,-0.635 on M2 Board Dimensions
-3.175,-17.399 to 22.225,-17.399 on M2 Board Dimensions
0,-1.524 to 0,63.5 on M2 Board Dimensions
